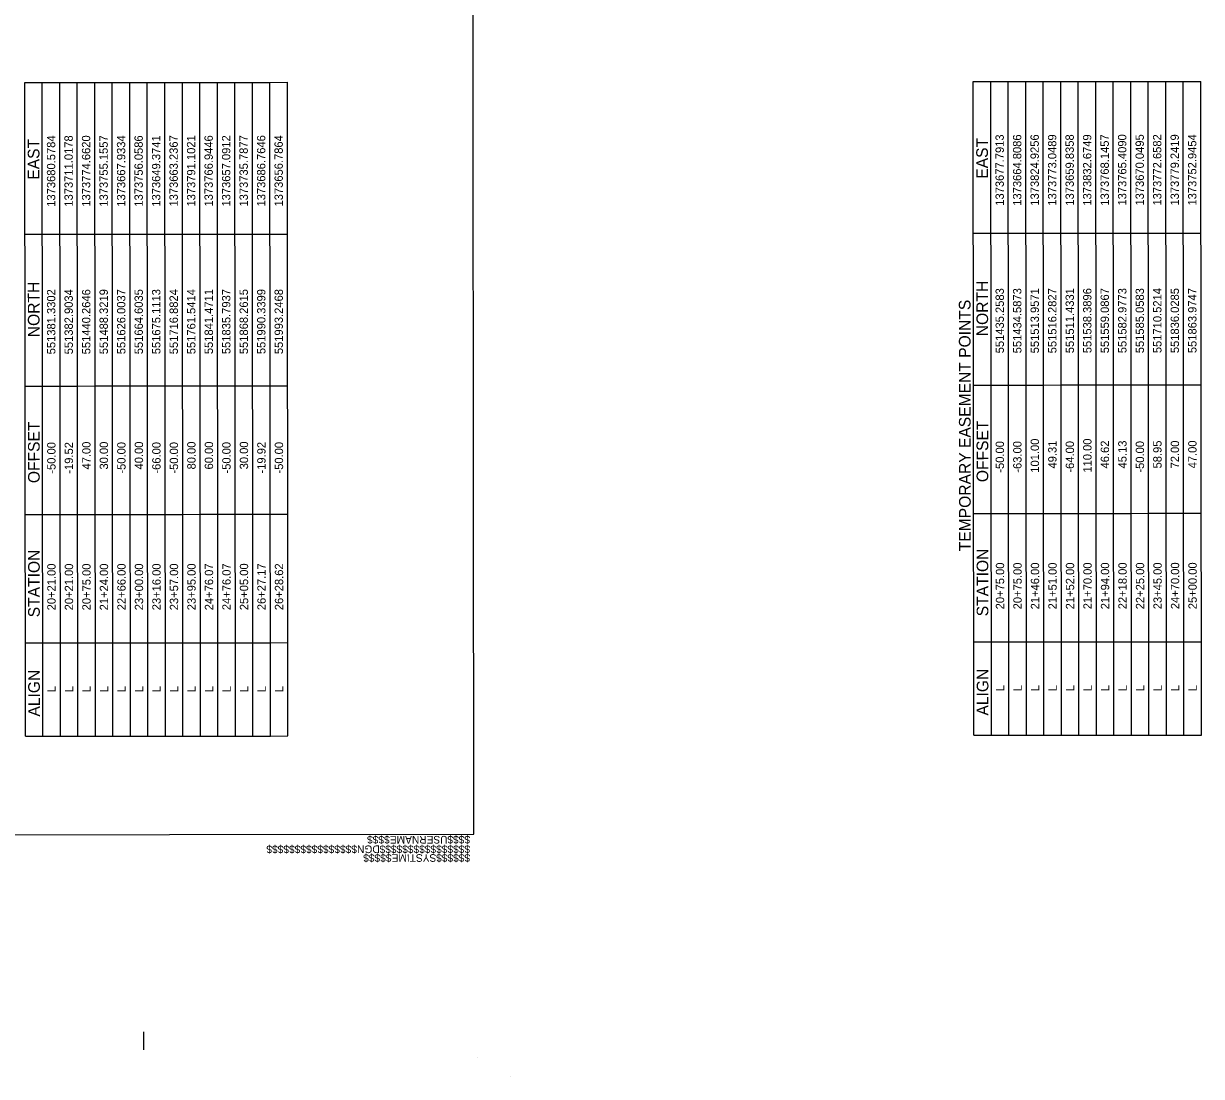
# Model space of a CAD drawing. Extents: x 1373043 to 1375788, y 550128 to 553055.
# Drawn here: x 1374375 to 1375788, y 550128 to 551391 of the extents above; entities that cross this region are included whole.
import ezdxf

# ---------------------------------------------------------------- set-up
doc = ezdxf.new("R2010")
doc.units = 0
for name, color, linetype in [('CTL Sheet Border CELL', 7, 'Continuous'), ('CTL Sheet Notes CELL', 7, 'Continuous'), ('CTL Sheet Table Cell', 7, 'Continuous'), ('CTL Sheet Text', 7, 'Continuous'), ('Scratch_Level_7', 7, 'Continuous')]:
    doc.layers.add(name, color=color, linetype=linetype)

msp = doc.modelspace()

# ---------------------------------------------------------------- linework, layer by layer
at = {"layer": 'CTL Sheet Border CELL'}
for p, q in [((1374914.6, 550418.2), (1374914.6, 550418.2)), ((1374914.6, 550418.2), (1374914.6, 550418.2)), ((1374914.6, 550418.2), (1374914.6, 550418.2)), ((1374914.6, 550418.2), (1374914.6, 550418.2)), ((1374914.6, 550418.2), (1374914.6, 550418.2)), ((1374914.6, 550418.2), (1374914.6, 550418.2)), ((1374914.6, 550418.2), (1374914.6, 550418.2)), ((1374914.6, 550418.2), (1374914.6, 550418.2)), ((1374914.6, 550418.2), (1374914.6, 550418.2)), ((1374914.6, 550418.2), (1374914.6, 550418.2)), ((1374914.6, 550418.2), (1374914.6, 550418.2)), ((1374519.1, 550159.6), (1374519.1, 550181.3)), ((1374919.2, 550150.3), (1374919.2, 550150.3)), ((1374958.3, 550127.8), (1374958.3, 550127.8))]:
    msp.add_line(p, q, dxfattribs=at)
msp.add_lwpolyline([(1373086.2, 553025.2), (1373088.5, 550416.5), (1374914.6, 550418.2), (1374912.2, 553026.9)], close=True, dxfattribs=at)
msp.add_lwpolyline([(1374914.5, 550483.4), (1374914.5, 550483.4)], dxfattribs=at)
msp.add_lwpolyline([(1374914.5, 550483.4), (1374914.5, 550483.4)], dxfattribs=at)
at = {"layer": 'CTL Sheet Table Cell'}
for p, q in [((1374376.8, 550535.8), (1374376.1, 551319.8)), ((1374376.1, 551319.8), (1374397.1, 551319.8)), ((1374397.8, 550535.8), (1374397.1, 551319.8)), ((1374397.1, 551319.8), (1374418.1, 551319.8)), ((1374418.8, 550535.8), (1374418.1, 551319.8)), ((1374418.1, 551319.8), (1374439.1, 551319.8)), ((1374439.1, 551319.8), (1374460.1, 551319.9)), ((1374439.8, 550535.8), (1374439.1, 551319.8)), ((1374460.8, 550535.9), (1374460.1, 551319.9)), ((1374460.1, 551319.9), (1374481.1, 551319.9)), ((1374481.8, 550535.9), (1374481.1, 551319.9)), ((1374481.1, 551319.9), (1374502.1, 551319.9)), ((1374502.8, 550535.9), (1374502.1, 551319.9)), ((1374502.1, 551319.9), (1374523.1, 551319.9)), ((1374523.8, 550535.9), (1374523.1, 551319.9)), ((1374523.1, 551319.9), (1374544.1, 551319.9)), ((1374544.8, 550535.9), (1374544.1, 551319.9)), ((1374544.1, 551319.9), (1374565.1, 551319.9)), ((1374565.1, 551319.9), (1374586.1, 551320)), ((1374565.8, 550535.9), (1374565.1, 551319.9)), ((1374586.8, 550536), (1374586.1, 551320)), ((1374586.1, 551320), (1374607.1, 551320)), ((1374607.8, 550536), (1374607.1, 551320)), ((1374607.1, 551320), (1374628.1, 551320)), ((1374628.8, 550536), (1374628.1, 551320)), ((1374628.1, 551320), (1374649.1, 551320)), ((1374649.8, 550536), (1374649.1, 551320)), ((1374649.1, 551320), (1374670.1, 551320)), ((1374670.1, 551320), (1374691.1, 551320.1)), ((1374670.8, 550536), (1374670.1, 551320)), ((1374691.8, 550536.1), (1374691.1, 551320.1)), ((1374376.2, 551137.8), (1374397.2, 551137.8)), ((1374397.2, 551137.8), (1374418.2, 551137.8)), ((1374418.2, 551137.8), (1374439.2, 551137.8)), ((1374439.2, 551137.8), (1374460.2, 551137.9)), ((1374460.2, 551137.9), (1374481.2, 551137.9)), ((1374481.2, 551137.9), (1374502.2, 551137.9)), ((1374502.2, 551137.9), (1374523.2, 551137.9)), ((1374523.2, 551137.9), (1374544.2, 551137.9)), ((1374544.2, 551137.9), (1374565.2, 551137.9)), ((1374565.2, 551137.9), (1374586.2, 551138)), ((1374586.2, 551138), (1374607.2, 551138)), ((1374607.2, 551138), (1374628.2, 551138)), ((1374628.2, 551138), (1374649.2, 551138)), ((1374649.2, 551138), (1374670.2, 551138)), ((1374670.2, 551138), (1374691.2, 551138.1)), ((1374376.4, 550955.8), (1374397.4, 550955.8)), ((1374397.4, 550955.8), (1374418.4, 550955.8)), ((1374418.4, 550955.8), (1374439.4, 550955.8)), ((1374439.4, 550955.8), (1374460.4, 550955.9)), ((1374460.4, 550955.9), (1374481.4, 550955.9)), ((1374481.4, 550955.9), (1374502.4, 550955.9)), ((1374502.4, 550955.9), (1374523.4, 550955.9)), ((1374523.4, 550955.9), (1374544.4, 550955.9)), ((1374544.4, 550955.9), (1374565.4, 550955.9)), ((1374565.4, 550955.9), (1374586.4, 550956)), ((1374586.4, 550956), (1374607.4, 550956)), ((1374607.4, 550956), (1374628.4, 550956)), ((1374628.4, 550956), (1374649.4, 550956)), ((1374649.4, 550956), (1374670.4, 550956)), ((1374670.4, 550956), (1374691.4, 550956.1)), ((1374376.5, 550801.8), (1374397.5, 550801.8)), ((1374397.5, 550801.8), (1374418.5, 550801.8)), ((1374418.5, 550801.8), (1374439.5, 550801.8)), ((1374439.5, 550801.8), (1374460.5, 550801.9)), ((1374460.5, 550801.9), (1374481.5, 550801.9)), ((1374481.5, 550801.9), (1374502.5, 550801.9)), ((1374502.5, 550801.9), (1374523.5, 550801.9)), ((1374523.5, 550801.9), (1374544.5, 550801.9)), ((1374544.5, 550801.9), (1374565.5, 550801.9)), ((1374565.5, 550801.9), (1374586.5, 550802)), ((1374586.5, 550802), (1374607.5, 550802)), ((1374607.5, 550802), (1374628.5, 550802)), ((1374628.5, 550802), (1374649.5, 550802)), ((1374649.5, 550802), (1374670.5, 550802)), ((1374670.5, 550802), (1374691.5, 550802.1)), ((1374376.7, 550647.8), (1374397.7, 550647.8)), ((1374397.7, 550647.8), (1374418.7, 550647.8)), ((1374418.7, 550647.8), (1374439.7, 550647.8)), ((1374439.7, 550647.8), (1374460.7, 550647.9)), ((1374460.7, 550647.9), (1374481.7, 550647.9)), ((1374481.7, 550647.9), (1374502.7, 550647.9)), ((1374502.7, 550647.9), (1374523.7, 550647.9)), ((1374523.7, 550647.9), (1374544.7, 550647.9)), ((1374544.7, 550647.9), (1374565.7, 550647.9)), ((1374565.7, 550647.9), (1374586.7, 550648)), ((1374586.7, 550648), (1374607.7, 550648)), ((1374607.7, 550648), (1374628.7, 550648)), ((1374628.7, 550648), (1374649.7, 550648)), ((1374649.7, 550648), (1374670.7, 550648)), ((1374670.7, 550648), (1374691.7, 550648.1)), ((1374376.8, 550535.8), (1374397.8, 550535.8)), ((1374397.8, 550535.8), (1374418.8, 550535.8)), ((1374418.8, 550535.8), (1374439.8, 550535.8)), ((1374439.8, 550535.8), (1374460.8, 550535.9)), ((1374460.8, 550535.9), (1374481.8, 550535.9)), ((1374481.8, 550535.9), (1374502.8, 550535.9)), ((1374502.8, 550535.9), (1374523.8, 550535.9)), ((1374523.8, 550535.9), (1374544.8, 550535.9)), ((1374544.8, 550535.9), (1374565.8, 550535.9)), ((1374565.8, 550535.9), (1374586.8, 550536)), ((1374586.8, 550536), (1374607.8, 550536)), ((1374607.8, 550536), (1374628.8, 550536)), ((1374628.8, 550536), (1374649.8, 550536)), ((1374649.8, 550536), (1374670.8, 550536)), ((1374670.8, 550536), (1374691.8, 550536.1))]:
    msp.add_line(p, q, dxfattribs=at)
at = {"layer": 'Scratch_Level_7'}
for p, q in [((1375514.6, 550537), (1375513.9, 551321)), ((1375513.9, 551321), (1375534.9, 551321)), ((1375535.6, 550537), (1375534.9, 551321)), ((1375534.9, 551321), (1375555.9, 551321)), ((1375556.6, 550537), (1375555.9, 551321)), ((1375555.9, 551321), (1375576.9, 551321)), ((1375577.6, 550537), (1375576.9, 551321)), ((1375576.9, 551321), (1375597.9, 551321)), ((1375597.9, 551321), (1375618.9, 551321.1)), ((1375598.6, 550537), (1375597.9, 551321)), ((1375619.6, 550537.1), (1375618.9, 551321.1)), ((1375618.9, 551321.1), (1375639.9, 551321.1)), ((1375640.6, 550537.1), (1375639.9, 551321.1)), ((1375639.9, 551321.1), (1375660.9, 551321.1)), ((1375661.6, 550537.1), (1375660.9, 551321.1)), ((1375660.9, 551321.1), (1375681.9, 551321.1)), ((1375682.6, 550537.1), (1375681.9, 551321.1)), ((1375681.9, 551321.1), (1375702.9, 551321.1)), ((1375702.9, 551321.1), (1375723.9, 551321.2)), ((1375703.6, 550537.1), (1375702.9, 551321.1)), ((1375724.6, 550537.2), (1375723.9, 551321.2)), ((1375723.9, 551321.2), (1375744.9, 551321.2)), ((1375745.6, 550537.2), (1375744.9, 551321.2)), ((1375744.9, 551321.2), (1375765.9, 551321.2)), ((1375766.6, 550537.2), (1375765.9, 551321.2)), ((1375765.9, 551321.2), (1375786.9, 551321.2)), ((1375787.6, 550537.2), (1375786.9, 551321.2)), ((1375514.1, 551139), (1375535.1, 551139)), ((1375535.1, 551139), (1375556.1, 551139)), ((1375556.1, 551139), (1375577.1, 551139)), ((1375577.1, 551139), (1375598.1, 551139)), ((1375598.1, 551139), (1375619.1, 551139.1)), ((1375619.1, 551139.1), (1375640.1, 551139.1)), ((1375640.1, 551139.1), (1375661.1, 551139.1)), ((1375661.1, 551139.1), (1375682.1, 551139.1)), ((1375682.1, 551139.1), (1375703.1, 551139.1)), ((1375703.1, 551139.1), (1375724.1, 551139.2)), ((1375724.1, 551139.2), (1375745.1, 551139.2)), ((1375745.1, 551139.2), (1375766.1, 551139.2)), ((1375766.1, 551139.2), (1375787.1, 551139.2)), ((1375514.3, 550957), (1375535.3, 550957)), ((1375535.3, 550957), (1375556.3, 550957)), ((1375556.3, 550957), (1375577.3, 550957)), ((1375577.3, 550957), (1375598.3, 550957)), ((1375598.3, 550957), (1375619.3, 550957.1)), ((1375619.3, 550957.1), (1375640.3, 550957.1)), ((1375640.3, 550957.1), (1375661.3, 550957.1)), ((1375661.3, 550957.1), (1375682.3, 550957.1)), ((1375682.3, 550957.1), (1375703.3, 550957.1)), ((1375703.3, 550957.1), (1375724.3, 550957.2)), ((1375724.3, 550957.2), (1375745.3, 550957.2)), ((1375745.3, 550957.2), (1375766.3, 550957.2)), ((1375766.3, 550957.2), (1375787.3, 550957.2)), ((1375514.4, 550803), (1375535.4, 550803)), ((1375535.4, 550803), (1375556.4, 550803)), ((1375556.4, 550803), (1375577.4, 550803)), ((1375577.4, 550803), (1375598.4, 550803)), ((1375598.4, 550803), (1375619.4, 550803.1)), ((1375619.4, 550803.1), (1375640.4, 550803.1)), ((1375640.4, 550803.1), (1375661.4, 550803.1)), ((1375661.4, 550803.1), (1375682.4, 550803.1)), ((1375682.4, 550803.1), (1375703.4, 550803.1)), ((1375703.4, 550803.1), (1375724.4, 550803.2)), ((1375724.4, 550803.2), (1375745.4, 550803.2)), ((1375745.4, 550803.2), (1375766.4, 550803.2)), ((1375766.4, 550803.2), (1375787.4, 550803.2)), ((1375514.5, 550649), (1375535.5, 550649)), ((1375535.5, 550649), (1375556.5, 550649)), ((1375556.5, 550649), (1375577.5, 550649)), ((1375577.5, 550649), (1375598.5, 550649)), ((1375598.5, 550649), (1375619.5, 550649.1)), ((1375619.5, 550649.1), (1375640.5, 550649.1)), ((1375640.5, 550649.1), (1375661.5, 550649.1)), ((1375661.5, 550649.1), (1375682.5, 550649.1)), ((1375682.5, 550649.1), (1375703.5, 550649.1)), ((1375703.5, 550649.1), (1375724.5, 550649.2)), ((1375724.5, 550649.2), (1375745.5, 550649.2)), ((1375745.5, 550649.2), (1375766.5, 550649.2)), ((1375766.5, 550649.2), (1375787.5, 550649.2)), ((1375514.6, 550537), (1375535.6, 550537)), ((1375535.6, 550537), (1375556.6, 550537)), ((1375556.6, 550537), (1375577.6, 550537)), ((1375577.6, 550537), (1375598.6, 550537)), ((1375598.6, 550537), (1375619.6, 550537.1)), ((1375619.6, 550537.1), (1375640.6, 550537.1)), ((1375640.6, 550537.1), (1375661.6, 550537.1)), ((1375661.6, 550537.1), (1375682.6, 550537.1)), ((1375682.6, 550537.1), (1375703.6, 550537.1)), ((1375703.6, 550537.1), (1375724.6, 550537.2)), ((1375724.6, 550537.2), (1375745.6, 550537.2)), ((1375745.6, 550537.2), (1375766.6, 550537.2)), ((1375766.6, 550537.2), (1375787.6, 550537.2))]:
    msp.add_line(p, q, dxfattribs=at)

# ---------------------------------------------------------------- texts
at = {"layer": 'CTL Sheet Border CELL'}
for s, p in [('$$$$$$$$$$$$$$$$DGN$$$$$$$$$$$$$$$$', (1374910.5, 550404.9)), ('$$$$USERNAME$$$$', (1374910.4, 550416.3)), ('$$$$$$SYSTIME$$$$$', (1374910.5, 550394.4))]:
    msp.add_text(s, height=9.13, rotation=180.0509, dxfattribs=at).set_placement(p)
at = {"layer": 'CTL Sheet Notes CELL'}
for s, p in [('EAST', (1374393.7, 551203.3)), ('NORTH', (1374393.8, 551014.4)), ('OFFSET', (1374394, 550839.4)), ('STATION', (1374394.1, 550678.5)), ('ALIGN', (1374394.2, 550559.4))]:
    msp.add_text(s, height=14, rotation=90.0509, dxfattribs=at).set_placement(p)
at = {"layer": 'CTL Sheet Text'}
for s, p in [('1373680.5784', (1374412.7, 551170.9)), ('1373711.0178', (1374433.7, 551171)), ('1373774.6620', (1374454.7, 551171)), ('1373755.1557', (1374475.7, 551171)), ('1373667.9334', (1374496.7, 551171)), ('1373756.0586', (1374517.7, 551171)), ('1373649.3741', (1374538.7, 551171)), ('1373663.2367', (1374559.7, 551171.1)), ('1373791.1021', (1374580.7, 551171.1)), ('1373766.9446', (1374601.7, 551171.1)), ('1373657.0912', (1374622.7, 551171.1)), ('1373735.7877', (1374643.7, 551171.1)), ('1373686.7646', (1374664.7, 551171.2)), ('1373656.7864', (1374685.7, 551171.2)), ('551381.3302', (1374412.8, 550993.9)), ('551382.9034', (1374433.8, 550993.9)), ('551440.2646', (1374454.8, 550993.9)), ('551488.3219', (1374475.8, 550994)), ('551626.0037', (1374496.8, 550994)), ('551664.6035', (1374517.8, 550994)), ('551675.1113', (1374538.8, 550994)), ('551716.8824', (1374559.8, 550994)), ('551761.5414', (1374580.8, 550994)), ('551841.4711', (1374601.8, 550994.1)), ('551835.7937', (1374622.8, 550994.1)), ('551868.2615', (1374643.8, 550994.1)), ('551990.3399', (1374664.8, 550994.1)), ('551993.2468', (1374685.8, 550994.1)), ('-50.00', (1374413, 550850.7)), ('-19.52', (1374434, 550850.7)), ('47.00', (1374455, 550855.7)), ('30.00', (1374476, 550855.7)), ('-50.00', (1374497, 550850.8)), ('40.00', (1374518, 550855.8)), ('-66.00', (1374539, 550850.8)), ('-50.00', (1374560, 550850.8)), ('80.00', (1374581, 550855.8)), ('60.00', (1374602, 550855.8)), ('-50.00', (1374623, 550850.9)), ('30.00', (1374644, 550855.9)), ('-19.92', (1374665, 550850.9)), ('-50.00', (1374686, 550850.9)), ('20+21.00', (1374413.1, 550686.8)), ('20+21.00', (1374434.1, 550686.8)), ('20+75.00', (1374455.1, 550686.8)), ('21+24.00', (1374476.1, 550686.8)), ('22+66.00', (1374497.1, 550686.9)), ('23+00.00', (1374518.1, 550686.9)), ('23+16.00', (1374539.1, 550686.9)), ('23+57.00', (1374560.1, 550686.9)), ('23+95.00', (1374581.1, 550686.9)), ('24+76.07', (1374602.1, 550686.9)), ('24+76.07', (1374623.1, 550687)), ('25+05.00', (1374644.1, 550687)), ('26+27.17', (1374665.1, 550687)), ('26+28.62', (1374686.1, 550687)), ('L', (1374413.2, 550588.5)), ('L', (1374434.2, 550588.5)), ('L', (1374455.2, 550588.5)), ('L', (1374476.2, 550588.6)), ('L', (1374497.2, 550588.6)), ('L', (1374518.2, 550588.6)), ('L', (1374539.2, 550588.6)), ('L', (1374560.2, 550588.6)), ('L', (1374581.2, 550588.7)), ('L', (1374602.2, 550588.7)), ('L', (1374623.2, 550588.7)), ('L', (1374644.2, 550588.7)), ('L', (1374665.2, 550588.7)), ('L', (1374686.2, 550588.7))]:
    msp.add_text(s, height=10, rotation=90.0509, dxfattribs=at).set_placement(p)
at = {"layer": 'Scratch_Level_7'}
for s, height, p in [('1373677.7913', 10, (1375550.6, 551172.1)), ('1373664.8086', 10, (1375571.6, 551172.1)), ('1373824.9256', 10, (1375592.6, 551172.2)), ('1373773.0489', 10, (1375613.6, 551172.2)), ('1373659.8358', 10, (1375634.6, 551172.2)), ('1373832.6749', 10, (1375655.6, 551172.2)), ('1373768.1457', 10, (1375676.6, 551172.2)), ('1373765.4090', 10, (1375697.6, 551172.3)), ('1373670.0495', 10, (1375718.6, 551172.3)), ('1373772.6582', 10, (1375739.6, 551172.3)), ('1373779.2419', 10, (1375760.6, 551172.3)), ('1373752.9454', 10, (1375781.6, 551172.3)), ('EAST', 14, (1375531.5, 551204.5)), ('NORTH', 14, (1375531.7, 551015.6)), ('551435.2583', 10, (1375550.7, 550995.1)), ('551434.5873', 10, (1375571.7, 550995.1)), ('551513.9571', 10, (1375592.7, 550995.1)), ('551516.2827', 10, (1375613.7, 550995.1)), ('551511.4331', 10, (1375634.7, 550995.2)), ('551538.3896', 10, (1375655.7, 550995.2)), ('551559.0867', 10, (1375676.7, 550995.2)), ('551582.9773', 10, (1375697.7, 550995.2)), ('551585.0583', 10, (1375718.7, 550995.2)), ('551710.5214', 10, (1375739.7, 550995.3)), ('551836.0285', 10, (1375760.7, 550995.3)), ('551863.9747', 10, (1375781.7, 550995.3)), ('TEMPORARY EASEMENT POINTS', 14, (1375510.9, 550757.7)), ('OFFSET', 14, (1375531.9, 550840.6)), ('-50.00', 10, (1375550.8, 550851.9)), ('-63.00', 10, (1375571.8, 550851.9)), ('101.00', 10, (1375592.8, 550851.9)), ('49.31', 10, (1375613.8, 550856.9)), ('-64.00', 10, (1375634.8, 550852)), ('110.00', 10, (1375655.8, 550852)), ('46.62', 10, (1375676.8, 550857)), ('45.13', 10, (1375697.8, 550857)), ('-50.00', 10, (1375718.8, 550852)), ('58.95', 10, (1375739.8, 550857)), ('72.00', 10, (1375760.8, 550857)), ('47.00', 10, (1375781.8, 550857.1)), ('STATION', 14, (1375532, 550679.7)), ('20+75.00', 10, (1375551, 550688)), ('20+75.00', 10, (1375572, 550688)), ('21+46.00', 10, (1375593, 550688)), ('21+51.00', 10, (1375614, 550688)), ('21+52.00', 10, (1375635, 550688)), ('21+70.00', 10, (1375656, 550688.1)), ('21+94.00', 10, (1375677, 550688.1)), ('22+18.00', 10, (1375698, 550688.1)), ('22+25.00', 10, (1375719, 550688.1)), ('23+45.00', 10, (1375740, 550688.1)), ('24+70.00', 10, (1375761, 550688.2)), ('25+00.00', 10, (1375782, 550688.2)), ('ALIGN', 14, (1375532.1, 550560.6)), ('L', 10, (1375551.1, 550589.7)), ('L', 10, (1375572.1, 550589.7)), ('L', 10, (1375593.1, 550589.7)), ('L', 10, (1375614.1, 550589.8)), ('L', 10, (1375635.1, 550589.8)), ('L', 10, (1375656.1, 550589.8)), ('L', 10, (1375677.1, 550589.8)), ('L', 10, (1375698.1, 550589.8)), ('L', 10, (1375719.1, 550589.8)), ('L', 10, (1375740.1, 550589.9)), ('L', 10, (1375761.1, 550589.9)), ('L', 10, (1375782.1, 550589.9))]:
    msp.add_text(s, height=height, rotation=90.0509, dxfattribs=at).set_placement(p)

doc.saveas('drawing.dxf')
